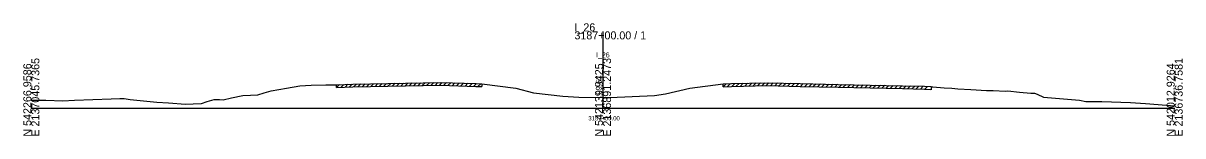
# Model space of a CAD drawing. Extents: x -13101 to 4803, y -924 to 22390.
# Drawn here: x 997.2 to 1402.8, y 12990.3 to 13029.6 of the extents above; entities that cross this region are included whole.
import ezdxf

# ---------------------------------------------------------------- set-up
doc = ezdxf.new("R2010")
doc.units = 0
for name, color, linetype in [('RD_GPK_XS_Cell', 7, 'Continuous'), ('RD_XS_ExGround', 7, 'Continuous'), ('RD_XS_ExPaveRet', 7, 'Continuous'), ('RD_XS_TX_Baseline', 7, 'Continuous'), ('RD_XS_TX_Elev_EX', 7, 'Continuous'), ('RD_XS_TX_Station', 7, 'Continuous')]:
    doc.layers.add(name, color=color, linetype=linetype)

msp = doc.modelspace()

# ---------------------------------------------------------------- linework, layer by layer
at = {"layer": 'RD_GPK_XS_Cell'}
for p, q in [((1200, 13000), (1200, 13026.78)), ((1000, 13000), (1200, 13000)), ((1200, 13000), (1400, 13000))]:
    msp.add_line(p, q, dxfattribs=at)
at = {"layer": 'RD_XS_ExGround'}
msp.add_lwpolyline([(1000, 13002.79), (1000.99, 13002.77), (1005.07, 13002.77), (1010.99, 13002.57), (1015.12, 13002.72), (1027.92, 13003.24), (1031, 13003.33), (1032.47, 13003.28), (1034.59, 13003.01), (1043.93, 13002.1), (1048.04, 13001.83), (1053.94, 13001.37), (1056.57, 13001.44), (1059.5, 13001.53), (1061.53, 13002.23), (1063.94, 13002.98), (1065.78, 13002.94), (1067.16, 13002.89), (1070.09, 13003.55), (1073.95, 13004.39), (1076.69, 13004.52), (1079.24, 13004.65), (1081.46, 13005.31), (1083.96, 13006.02), (1089.27, 13006.96), (1093.96, 13007.78), (1097.91, 13007.95), (1103.03, 13008.15), (1106.74, 13008.16), (1112.49, 13008.36), (1130.86, 13008.72), (1143.32, 13008.93), (1155.5, 13008.54), (1157.63, 13008.47), (1169.56, 13006.97), (1175.63, 13005.32), (1185.95, 13004.14), (1191.55, 13003.85), (1200, 13003.67), (1202.35, 13003.64), (1218.07, 13004.4), (1221.84, 13005.01), (1230.41, 13006.99), (1242.07, 13008.46), (1244.93, 13008.55), (1257.4, 13008.84), (1268.98, 13008.57), (1282.27, 13008.27), (1287.8, 13008.14), (1304.72, 13007.8), (1312.53, 13007.58), (1314.71, 13007.5), (1314.76, 13007.37), (1315.34, 13007.42), (1319.38, 13007.11), (1322.01, 13006.89), (1324.13, 13006.72), (1328.64, 13006.43), (1334.14, 13006.13), (1336.53, 13006.16), (1340.85, 13005.89), (1341.62, 13005.97), (1345.74, 13005.52), (1349.7, 13005.21), (1350.66, 13005.15), (1350.98, 13005.15), (1351.93, 13004.81), (1354.16, 13003.8), (1358.3, 13003.42), (1366.68, 13002.69), (1368.89, 13002.33), (1371.09, 13002.31), (1374.51, 13002.33), (1384.51, 13001.92), (1389.76, 13001.6), (1400, 13000.78)], dxfattribs=at)
at = {"layer": 'RD_XS_ExPaveRet'}
for p, q in [((1106.74, 13007.16), (1107.78, 13008.2)), ((1106.74, 13007.16), (1106.74, 13008.16)), ((1106.74, 13007.16), (1112.49, 13007.36)), ((1108.24, 13007.21), (1109.28, 13008.25)), ((1109.74, 13007.26), (1110.78, 13008.3)), ((1111.24, 13007.31), (1112.28, 13008.35)), ((1112.49, 13007.36), (1130.86, 13007.72)), ((1112.74, 13007.36), (1113.76, 13008.38)), ((1114.24, 13007.39), (1115.26, 13008.41)), ((1115.74, 13007.42), (1116.76, 13008.44)), ((1117.24, 13007.45), (1118.26, 13008.47)), ((1118.74, 13007.48), (1119.76, 13008.5)), ((1120.24, 13007.51), (1121.26, 13008.53)), ((1121.74, 13007.54), (1122.76, 13008.56)), ((1123.24, 13007.57), (1124.26, 13008.59)), ((1124.74, 13007.6), (1125.76, 13008.62)), ((1126.24, 13007.63), (1127.26, 13008.65)), ((1127.74, 13007.66), (1128.76, 13008.68)), ((1129.24, 13007.68), (1130.26, 13008.7)), ((1130.74, 13007.71), (1131.76, 13008.73)), ((1130.86, 13007.72), (1143.32, 13007.93)), ((1132.24, 13007.74), (1133.26, 13008.76)), ((1133.74, 13007.77), (1134.76, 13008.78)), ((1135.24, 13007.79), (1136.26, 13008.81)), ((1136.74, 13007.82), (1137.76, 13008.83)), ((1138.24, 13007.84), (1139.26, 13008.86)), ((1139.74, 13007.87), (1140.76, 13008.88)), ((1141.24, 13007.89), (1142.26, 13008.91)), ((1142.74, 13007.92), (1143.74, 13008.91)), ((1143.32, 13007.93), (1155.5, 13007.54)), ((1144.24, 13007.9), (1145.21, 13008.87)), ((1145.74, 13007.85), (1146.71, 13008.82)), ((1147.24, 13007.8), (1148.21, 13008.77)), ((1148.74, 13007.75), (1149.71, 13008.72)), ((1150.24, 13007.71), (1151.21, 13008.67)), ((1151.74, 13007.66), (1152.71, 13008.63)), ((1153.24, 13007.61), (1154.21, 13008.58)), ((1154.74, 13007.56), (1155.71, 13008.53)), ((1155.5, 13007.54), (1157.63, 13007.47)), ((1156.24, 13007.51), (1157.21, 13008.48)), ((1157.63, 13008.47), (1157.63, 13007.47)), ((1242.07, 13007.46), (1243.1, 13008.49)), ((1242.07, 13007.46), (1242.07, 13008.46)), ((1242.07, 13007.46), (1244.93, 13007.55)), ((1243.57, 13007.5), (1244.6, 13008.54)), ((1244.93, 13007.55), (1257.4, 13007.84)), ((1245.07, 13007.55), (1246.09, 13008.57)), ((1246.57, 13007.59), (1247.59, 13008.61)), ((1248.07, 13007.62), (1249.09, 13008.64)), ((1249.57, 13007.66), (1250.59, 13008.68)), ((1251.07, 13007.69), (1252.09, 13008.71)), ((1252.57, 13007.72), (1253.59, 13008.75)), ((1254.07, 13007.76), (1255.09, 13008.78)), ((1255.57, 13007.79), (1256.59, 13008.82)), ((1257.07, 13007.83), (1258.06, 13008.82)), ((1257.4, 13007.84), (1268.98, 13007.57)), ((1258.57, 13007.81), (1259.54, 13008.79)), ((1260.07, 13007.78), (1261.04, 13008.75)), ((1261.57, 13007.74), (1262.54, 13008.72)), ((1263.07, 13007.71), (1264.04, 13008.68)), ((1264.57, 13007.67), (1265.54, 13008.65)), ((1266.07, 13007.64), (1267.04, 13008.61)), ((1267.57, 13007.6), (1268.54, 13008.58)), ((1268.98, 13007.57), (1282.27, 13007.27)), ((1269.07, 13007.57), (1270.04, 13008.55)), ((1270.57, 13007.53), (1271.54, 13008.51)), ((1272.07, 13007.5), (1273.04, 13008.48)), ((1273.57, 13007.47), (1274.54, 13008.45)), ((1275.07, 13007.43), (1276.04, 13008.41)), ((1276.57, 13007.4), (1277.54, 13008.38)), ((1278.07, 13007.37), (1279.04, 13008.35)), ((1279.57, 13007.33), (1280.54, 13008.31)), ((1281.07, 13007.3), (1282.04, 13008.28)), ((1282.27, 13007.27), (1287.8, 13007.14)), ((1282.57, 13007.27), (1283.54, 13008.24)), ((1284.07, 13007.23), (1285.04, 13008.2)), ((1285.57, 13007.19), (1286.54, 13008.17)), ((1287.07, 13007.15), (1288.04, 13008.13)), ((1287.8, 13007.14), (1304.72, 13006.8)), ((1288.57, 13007.12), (1289.55, 13008.1)), ((1290.07, 13007.09), (1291.05, 13008.07)), ((1291.57, 13007.06), (1292.55, 13008.04)), ((1293.07, 13007.03), (1294.05, 13008.01)), ((1294.57, 13007), (1295.55, 13007.98)), ((1296.07, 13006.97), (1297.05, 13007.95)), ((1297.57, 13006.94), (1298.55, 13007.93)), ((1299.07, 13006.91), (1300.05, 13007.9)), ((1300.57, 13006.89), (1301.55, 13007.87)), ((1302.07, 13006.86), (1303.05, 13007.84)), ((1303.57, 13006.83), (1304.55, 13007.81)), ((1304.72, 13006.8), (1312.53, 13006.58)), ((1305.07, 13006.79), (1306.04, 13007.77)), ((1306.57, 13006.75), (1307.54, 13007.72)), ((1308.07, 13006.71), (1309.04, 13007.68)), ((1309.57, 13006.66), (1310.54, 13007.64)), ((1311.07, 13006.62), (1312.04, 13007.59)), ((1312.53, 13006.58), (1314.71, 13006.5)), ((1312.57, 13006.58), (1313.53, 13007.54)), ((1314.71, 13006.5), (1314.76, 13006.37)), ((1314.76, 13007.37), (1314.76, 13006.37))]:
    msp.add_line(p, q, dxfattribs=at)

# ---------------------------------------------------------------- texts
at = {"layer": 'RD_GPK_XS_Cell'}
for s, p in [('3187+00.00 / 1', (1190, 13023.98)), ('I_26', (1190, 13026.78))]:
    msp.add_text(s, height=2.8, dxfattribs=at).set_placement(p)
for s, p in [('N 542266.9586', (1000, 12990)), ('E 2137045.7365', (1002.8, 12990)), ('N 542139.9425', (1200, 12990)), ('E 2136891.2473', (1202.8, 12990)), ('N 542012.9264', (1400, 12990)), ('E 2136736.7581', (1402.8, 12990))]:
    msp.add_text(s, height=2.8, rotation=90, dxfattribs=at).set_placement(p)
at = {"layer": 'RD_XS_TX_Baseline'}
msp.add_text('I_26', height=1.75, dxfattribs=at).set_placement((1197.6, 13017.67))
at = {"layer": 'RD_XS_TX_Elev_EX'}
msp.add_text('99.67', height=2, rotation=90, dxfattribs=at).set_placement((1199.5, 13004.67))
at = {"layer": 'RD_XS_TX_Station'}
msp.add_text('3187+00.00', height=1.5, dxfattribs=at).set_placement((1194.87, 12995.67))

doc.saveas('drawing.dxf')
